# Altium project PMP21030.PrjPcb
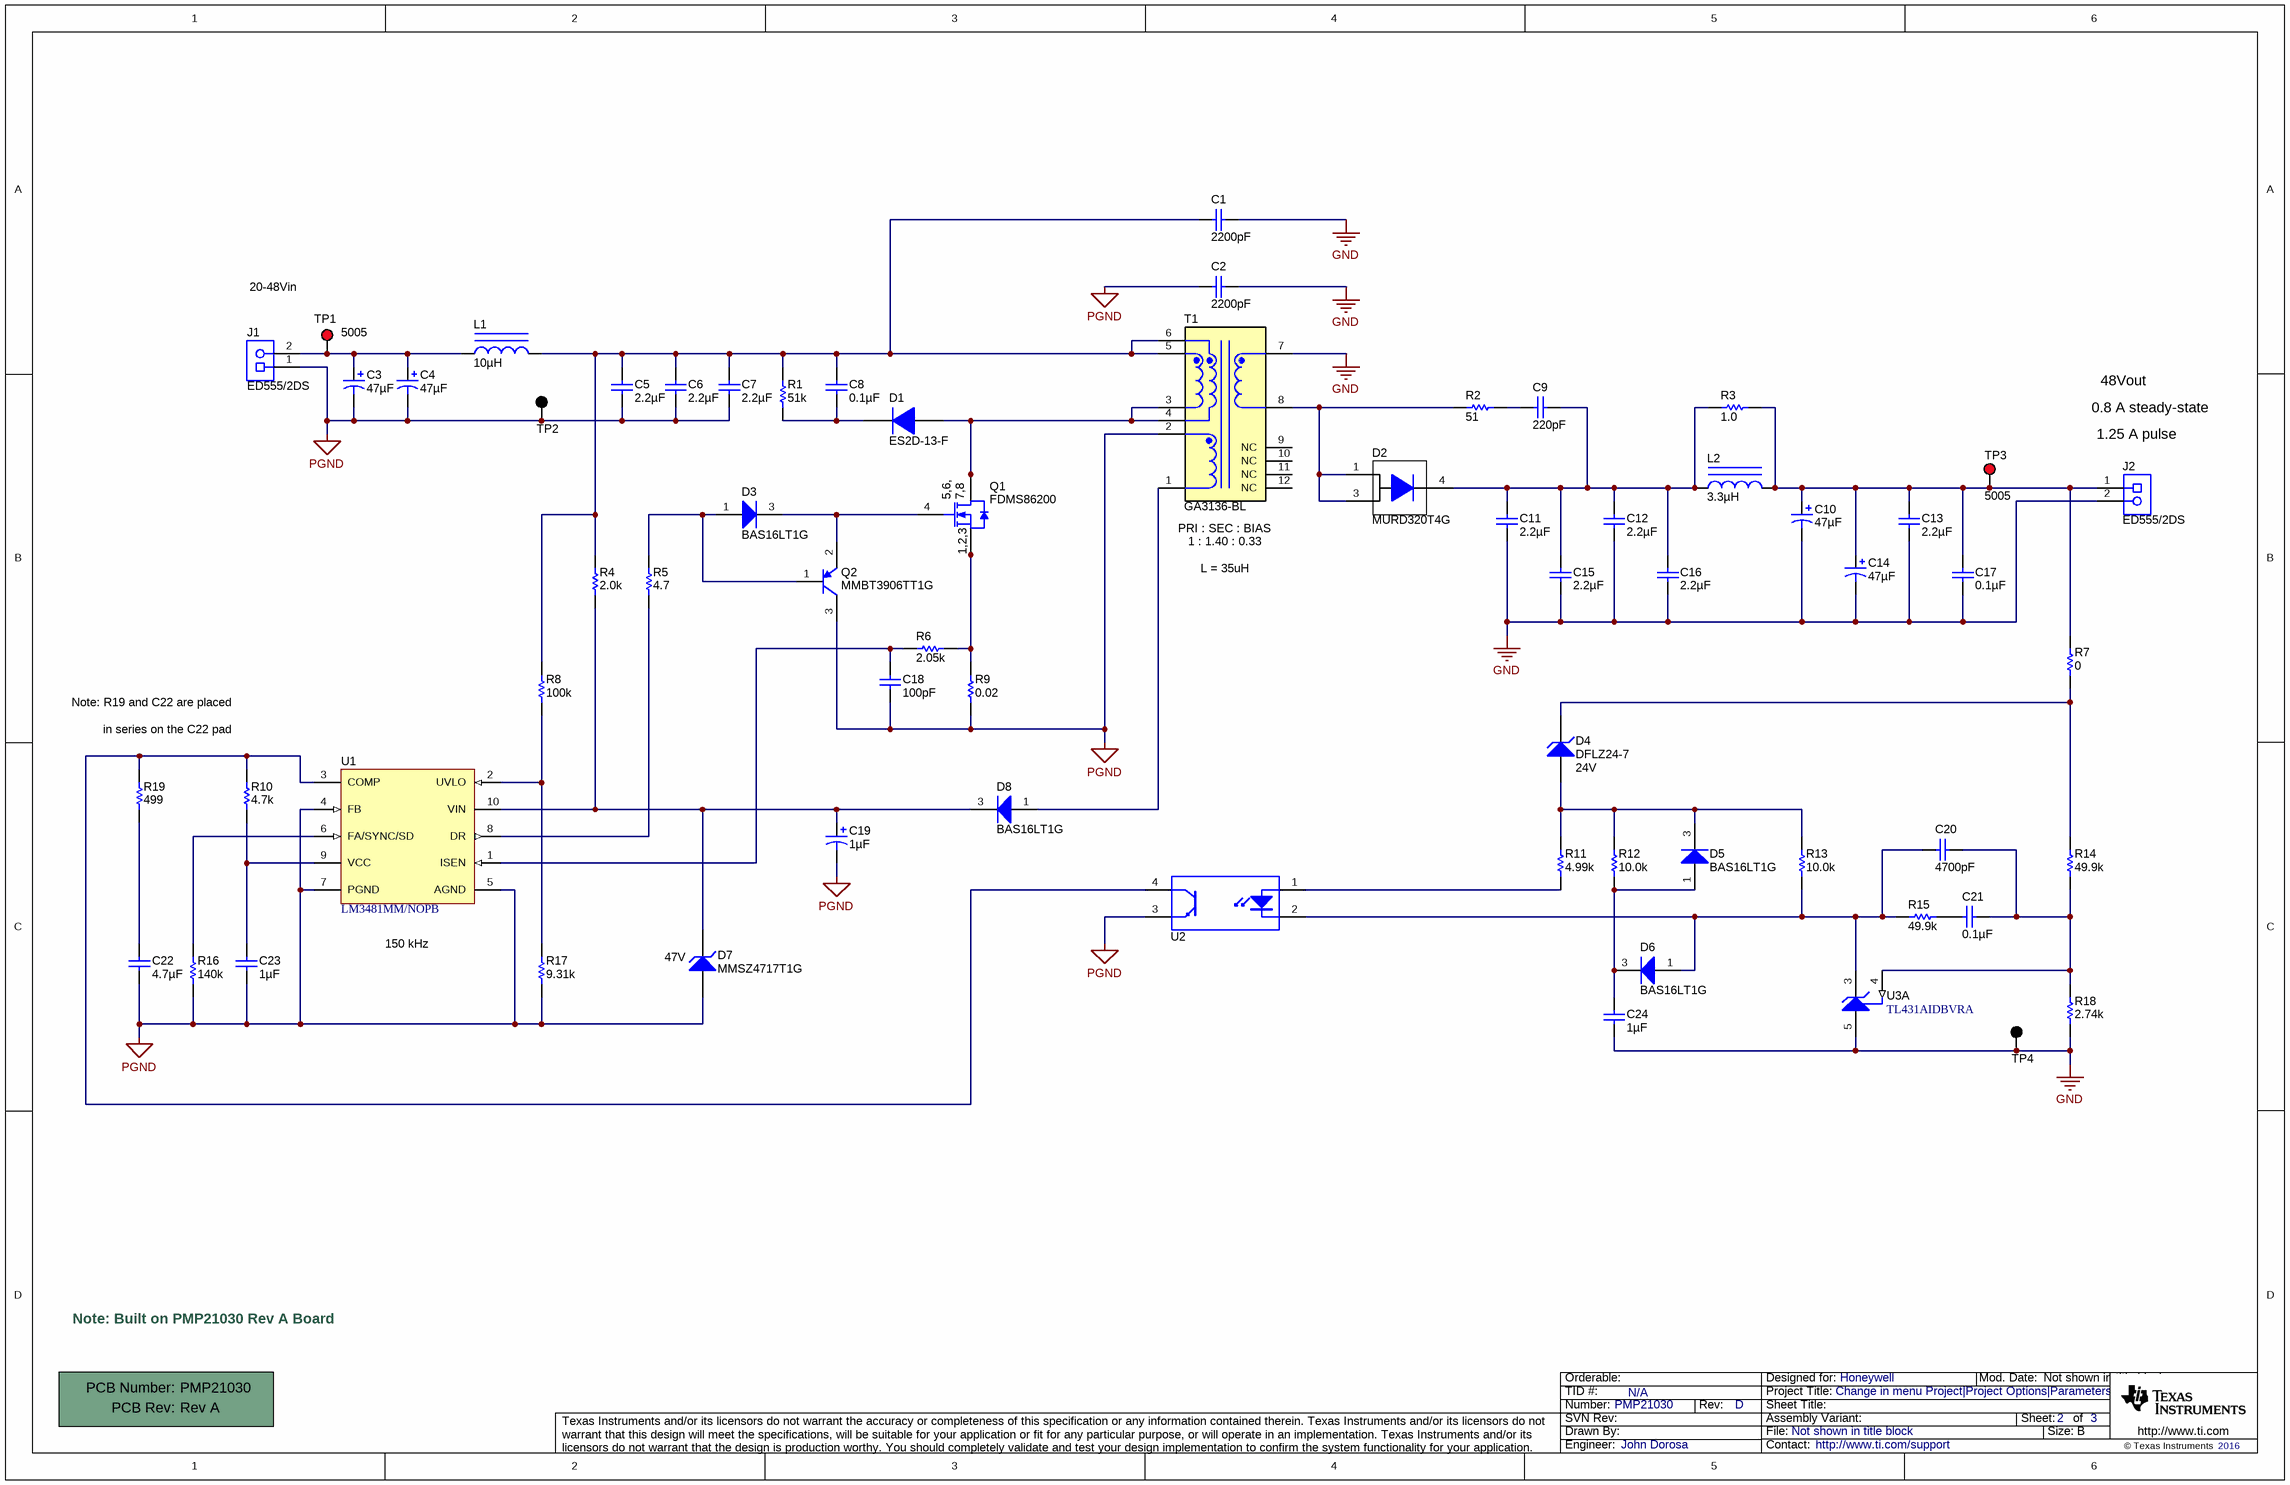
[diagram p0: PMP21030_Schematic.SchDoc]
TID: N/A; TechSupport: http://www.ti.com/support; SCH_Rev: D; PRJ_Title: Change in menu Project|Project Options|Parameters; PRJ_Number: PMP21030; PRJ_Engineer: John Dorosa; PRJ_Customer: Honeywell; PCB_Rev: Rev A; PCB_Layout: John Dorosa; CopyrightYear: 2016
1 sheet, 66 parts. Net scope: global (net labels, ports and power ports of the same name join across sheets).
Board file: PMP21030_PCB.PcbDoc

## Sheet PMP21030_Schematic.SchDoc
size 431 x 279 mm; Date: Not shown in title block; ApprovedBy: Not shown in title block; CheckedBy: Not shown in title block; Author: Not shown in title block; CompanyName: Not shown in title block; Engineer: Not shown in title block; Organization: Not shown in title block; Address1: Not shown in title block; Address2: Not shown in title block; Address3: Not shown in title block; Address4: Not shown in title block; DocumentNumber: 1; Revision: Use project parameter SCH_Rev; SheetNumber: 2; SheetTotal: 3; PageSetup: Record=PageOptions¦CenterHorizontal=True¦CenterVertical=True¦PrintScale=1.00¦XCorrection=1.00¦YCorrection=1.00¦PrintKind=0¦BorderSize=5000000¦LeftOffset=0¦BottomOffset=0¦Orientation=2¦PaperLength=1000¦PaperWidth=1000¦Scale=100¦PaperSource=15¦PrintQuality=600¦MediaType=1¦DitherType=10¦PaperKind=Letter¦PrintScaleMode=1

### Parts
!PCB  Printed Circuit Board  (value not drawn)  (mechanical)
C1  ValueDisplayed: 2200pF  [1812]  (hidden comment: C4532X7R3D222K130KA)
C2  ValueDisplayed: 2200pF  [1812]  (hidden comment: C4532X7R3D222K130KA)
C3  ValueDisplayed: 47µF  [SM_RADIAL_F]  (hidden comment: EEE-FK1J470P)
C4  ValueDisplayed: 47µF  [SM_RADIAL_F]  (hidden comment: EEE-FK1J470P)
C5  ValueDisplayed: 2.2µF  [1206l]  (hidden comment: C3216X7S2A225K160AB)
C6  ValueDisplayed: 2.2µF  [1206l]  (hidden comment: C3216X7S2A225K160AB)
C7  ValueDisplayed: 2.2µF  [1206l]  (hidden comment: C3216X7S2A225K160AB)
C8  ValueDisplayed: 0.1µF  [0603L]  (hidden comment: GCJ188R72A104KA01D)
C9  ValueDisplayed: 220pF  [1206L]  (hidden comment: GRM31A7U2J221JW31D)
C10  ValueDisplayed: 47µF  [SM_RADIAL_F]  (hidden comment: EEE-FK1J470P)
C11  ValueDisplayed: 2.2µF  [1206l]  (hidden comment: C3216X7S2A225K160AB)
C12  ValueDisplayed: 2.2µF  [1206l]  (hidden comment: C3216X7S2A225K160AB)
C13  ValueDisplayed: 2.2µF  [1206l]  (hidden comment: C3216X7S2A225K160AB)
C14  ValueDisplayed: 47µF  [SM_RADIAL_F]  (hidden comment: EEE-FK1J470P)
C15  ValueDisplayed: 2.2µF  [1206l]  (hidden comment: C3216X7S2A225K160AB)
C16  ValueDisplayed: 2.2µF  [1206l]  (hidden comment: C3216X7S2A225K160AB)
C17  ValueDisplayed: 0.1µF  [1206l]  (hidden comment: GRM31CR72D104KW03L)
C18  ValueDisplayed: 100pF  [0603L]  (hidden comment: GRM1885C2A101JA01D)
C19  ValueDisplayed: 1µF  [Chemi-Con_500x1100]  (hidden comment: EKMG101ELL1R0ME11D)
C20  ValueDisplayed: 4700pF  [0603L]  (hidden comment: GCM188R71H472KA37D)
C21  ValueDisplayed: 0.1µF  [0603L]  (hidden comment: C1608X7R1E104K080AA)
C22  ValueDisplayed: 4.7µF  [0402L]  (hidden comment: GRM155R61E475ME15)
C23  ValueDisplayed: 1µF  [0805L]  (hidden comment: GRM219R71E105KA88D)
C24  ValueDisplayed: 1µF  [0603L]  (hidden comment: GCM188R71E105KA64D)
D1  ES2D-13-F  [SMB]
D2  MURD320T4G  [DPAK]
D3  BAS16LT1G  [SOT-23]
D4  DFLZ24-7  value 24V  [PowerDI123]
D5  BAS16LT1G  [SOT-23]
D6  BAS16LT1G  [SOT-23]
D7  MMSZ4717T1G  [SOD-123]
D8  BAS16LT1G  [SOT-23]
J1  ED555/2DS  [TERM_BLK_ED555-2DS]
J2  ED555/2DS  [TERM_BLK_ED555-2DS]
L1  ValueDisplayed: 10µH  [MSS1048]  (hidden comment: MSS1048-103MLB)
L2  ValueDisplayed: 3.3µH  [LPS4018]  (hidden comment: LPS4018-332MLB)
Q1  FDMS86200  [TRANS_Fairchild_PQFN08A]
Q2  MMBT3906TT1G  [SOT-416]
R1  ValueDisplayed: 51k  [2010L]  (hidden comment: CRCW201051K0JNEF)
R2  ValueDisplayed: 51  [2512]  (hidden comment: CRCW251251R0JNEG)
R3  ValueDisplayed: 1.0  [1206]  (hidden comment: CRCW12061R00JNEA)
R4  ValueDisplayed: 2.0k  [0805L]  (hidden comment: CRCW08052K00JNEA)
R5  ValueDisplayed: 4.7  [0603L]  (hidden comment: CRCW06034R70JNEA)
R6  ValueDisplayed: 2.05k  [0603L]  (hidden comment: CRCW06032K05FKEA)
R7  ValueDisplayed: 0  [0603L]  (hidden comment: CRCW06030000Z0EA)
R8  ValueDisplayed: 100k  [0603L]  (hidden comment: CRCW0603100KFKEA)
R9  ValueDisplayed: 0.02  [1206L]  (hidden comment: WSLP1206R0200FEA)
R10  ValueDisplayed: 4.7k  [0805L]  (hidden comment: CRCW08054K70JNEA)
R11  ValueDisplayed: 4.99k  [0603L]  (hidden comment: CRCW06034K99FKEA)
R12  ValueDisplayed: 10.0k  [0603L]  (hidden comment: CRCW060310K0FKEA)
R13  ValueDisplayed: 10.0k  [0603L]  (hidden comment: CRCW060310K0FKEA)
R14  ValueDisplayed: 49.9k  [0603L]  (hidden comment: CRCW060349K9FKEA)
R15  ValueDisplayed: 49.9k  [0603L]  (hidden comment: CRCW060349K9FKEA)
R16  ValueDisplayed: 140k  [0603L]  (hidden comment: CRCW0603140KFKEA)
R17  ValueDisplayed: 9.31k  [0603L]  (hidden comment: CRCW06039K31FKEA)
R18  ValueDisplayed: 2.74k  [0603L]  (hidden comment: CRCW06032K74FKEA)
R19  ValueDisplayed: 499  [0402L]  (hidden comment: CRCW0402499RFKED)
T1  GA3136-BL  [Coilcraft_GA3136-BL]
TP1  5005  [Keystone5005]
TP2  5006  [Keystone5006]  (value not drawn)
TP3  5005  [Keystone5005]
TP4  5006  [Keystone5006]  (value not drawn)
U1  LM3481MM/NOPB  [MUB10A_N]
U2  TCMT1107  [SOP-4]  (value not drawn)
U3  TL431AIDBVRA  [DBV0005A_N]  (part A of 2)

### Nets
GND: C1.1 C2.1 C10.2(-) C11.2 C12.2 C13.2 C14.2(-) C15.2 C16.2 C17.2 C24.2 J2.2 R18.1 T1.7 TP4.1 U3.5(ANODE)
PGND: C2.2 C3.2(-) C4.2(-) C5.2 C6.2 C7.2 C18.2 C19.2(-) C22.2 C23.2 D7.2(A) J1.1 Q2.3(C) R9.1 R16.2 R17.1 T1.2 TP2.1 U1.4(FB) U1.5(AGND) U1.7(PGND) U2.3(E)
NetC1_2: C1.2 C5.1 C6.1 C7.1 C8.1 L1.2 R1.2 R4.2 R8.2 T1.5 T1.6
NetC3_1: C3.1(+) C4.1(+) J1.2 L1.1 TP1.1
NetC8_2: C8.2 D1.1(K) R1.1
NetC9_1: C9.1 C11.1 C12.1 C15.1 C16.1 D2.4(K) L2.1 R3.1
NetC9_2: C9.2 R2.2
NetC10_1: C10.1(+) C13.1 C14.1(+) C17.1 J2.1 L2.2 R3.2 R7.2 TP3.1
NetC18_1: C18.1 R6.1 U1.1(ISEN)
NetC19_1: C19.1(+) D7.1(K) D8.3(K) R4.1 U1.10(VIN)
NetC20_1: C20.1 C21.1 R14.1 R18.2 U3.4(REF)
NetC20_2: C20.2 D6.1(A) R13.1 R15.2 U2.2(K) U3.3(CATHODE)
NetC21_2: C21.2 R15.1
NetC22_1: C22.1 R19.1
NetC23_1: C23.1 R10.1 U1.9(VCC)
NetC24_1: C24.1 D5.1(A) D6.3(K) R12.1
NetD1_2: D1.2(A) Q1.5(D) Q1.6(D) Q1.7(D) Q1.8(D) T1.3 T1.4
NetD2_1: D2.1(A) D2.3(A) R2.1 T1.8
NetD3_1: D3.1(A) Q2.1(B) R5.2
NetD3_3: D3.3(K) Q1.4(G) Q2.2(E)
NetD4_1: D4.1(K) R7.1 R14.2
NetD4_2: D4.2(A) D5.3(K) R11.2 R12.2 R13.2
NetD8_1: D8.1(A) T1.1
NetQ1_1: Q1.1(S) Q1.2(S) Q1.3(S) R6.2 R9.2
NetR5_1: R5.1 U1.8(DR)
NetR8_1: R8.1 R17.2 U1.2(UVLO)
NetR10_2: R10.2 R19.2 U1.3(COMP) U2.4(C)
NetR11_1: R11.1 U2.1(A)
NetR16_1: R16.1 U1.6(FA/SYNC/SD)

Not connected (* = marked no-connect by the designer): T1 9(NC) 10(NC) 11(NC) 12(NC)

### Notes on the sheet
- 20-48Vin
- 48Vout
- (near J2) 1.25 A pulse
- 0.8 A steady-state
- (near T1) PRI : SEC : BIAS
- (near T1) 1 : 1.40 : 0.33
- L = 35uH
- Note: R19 and C22 are placed
- in series on the C22 pad
- (near U1) 150 kHz
- (near D7) 47V
- Note: Built on PMP21030 Rev A Board

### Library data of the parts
!PCB = PCB: Manufacturer: Any; PartNumber: PMP21030; SymbolCreator: a0412235
C1 C2 = C4532X7R3D222K130KA: CAP, CERM, 2200 pF, 2000 V,+/- 10%, X7R, 1812; Manufacturer: TDK; Polarized: N; CompType: Capacitor; Value: 2200pF; U/M: EA; Cap_F: 0.0000000022; Tolerance_%: 10; VDC_V: 2000; Value2: 2000V; TaMin_C: -55; TaMax_C: 125; SizeArea_mm2: 14.4; SizeAreaWB_mm2: 23.1; SizeX_mm: 4.5; SizeY_mm: 3.2; SizeZ_mm: 1.35; AEC Category: Q200; Green_Lifecycle: Active; Green_REACh: Passed
C3 C4 C10 C14 = EEE-FK1J470P: CAP, AL, 47 µF, 63 V, +/- 20%, 0.65 ohm, AEC-Q200 Grade 2, SMD; Manufacturer: Panasonic; Polarized: Y; CompType: Capacitor; Value: 47uF; U/M: EA; Cap_F: 0.000047; Tolerance_%: 20; VDC_V: 63; Value2: 63V; ESR_ohm: 0.65; IRMS_A: 0.25; TaMin_C: -55; TaMax_C: 105; Cap_Case: F; SizeAreaWB_mm2: 123.6; SizeArea_mm2: 83; SizeX_mm: 10; SizeY_mm: 8.3; SizeZ_mm: 10.2; AEC Category: Q200; AEC Grade: 2; Green_Lifecycle: Active; Green_REACh: Passed
C5-C7 C11-C13 C15 C16 = C3216X7S2A225K160AB: CAP, CERM, 2.2 µF, 100 V,+/- 10%, X7S, 1206; Manufacturer: TDK; Polarized: N; CompType: Capacitor; Value: 2.2uF; U/M: EA; Cap_F: 0.0000022; Tolerance_%: 10; ESR_ohm: 0.005718; Value1: 0.005718 ohm; VDC_V: 100; Value2: 100V; IRMS_A: 3.03632; TaMin_C: -55; TaMax_C: 125; Cap_Case: 1206; SizeArea_mm2: 5.12; SizeAreaWB_mm2: 10.92; SizeX_mm: 3.2; SizeY_mm: 1.6; SizeZ_mm: 1.8; AEC Category: Q200
C8 = GCJ188R72A104KA01D: CAP, CERM, 0.1 µF, 100 V,+/- 10%, X7R, AEC-Q200 Grade 1, 0603; Manufacturer: MuRata; Polarized: N; CompType: Capacitor; Value: 0.1uF; U/M: EA; Cap_F: 0.0000001; Tolerance_%: 10; VDC_V: 100; Value2: 100V; TaMin_C: -55; TaMax_C: 125; Cap_Case: 0603; SizeArea_mm2: 1.28; SizeAreaWB_mm2: 4.68; SizeX_mm: 1.6; SizeY_mm: 0.8; SizeZ_mm: 1; AEC Category: Q200; AEC Qualified: Y
C9 = GRM31A7U2J221JW31D: CAP, CERM, 220 pF, 630 V,+/- 5%, U2J, 1206; Manufacturer: MuRata; Polarized: N; CompType: Capacitor; Value: 220pF; U/M: EA; Cap_F: 0.00000000022; Tolerance_%: 5; VDC_V: 630; Value2: 630V; TaMin_C: -55; TaMax_C: 125; Cap_Case: 1206; SizeArea_mm2: 5.12; SizeAreaWB_mm2: 10.92; SizeX_mm: 3.2; SizeY_mm: 1.6; SizeZ_mm: 1.35; AEC Category: Q200
C17 = GRM31CR72D104KW03L: CAP, CERM, 0.1 µF, 200 V,+/- 10%, X7R, 1206; Manufacturer: MuRata; Polarized: N; CompType: Capacitor; Value: 0.1uF; U/M: EA; Cap_F: 0.0000001; Tolerance_%: 10; VDC_V: 200; Value2: 200V; TaMin_C: -55; TaMax_C: 125; Cap_Case: 1206; SizeArea_mm2: 5.12; SizeAreaWB_mm2: 10.92; SizeX_mm: 3.2; SizeY_mm: 1.6; SizeZ_mm: 1.8; AEC Category: Q200
C18 = GRM1885C2A101JA01D: CAP, CERM, 100 pF, 100 V,+/- 5%, C0G/NP0, 0603; Manufacturer: MuRata; Polarized: N; CompType: Capacitor; Value: 100pF; U/M: EA; Cap_F: 0.0000000001; Tolerance_%: 5; VDC_V: 100; Value2: 100V; TaMin_C: -55; TaMax_C: 125; Cap_Case: 0603; SizeArea_mm2: 1.28; SizeAreaWB_mm2: 4.68; SizeX_mm: 1.6; SizeY_mm: 0.8; SizeZ_mm: 1; AEC Category: Q200; Green_Lifecycle: Active; Green_REACh: Passed
C19 = EKMG101ELL1R0ME11D: CAP, AL, 1 µF, 100 V, +/- 20%, TH; Manufacturer: Chemi-Con; Polarized: Y; CompType: Capacitor; Value: 1uF; U/M: EA; Cap_F: 0.000001; Tolerance_%: 20; VDC_V: 100; Value2: 100V; IRMS_A: 0.015; TaMin_C: -55; TaMax_C: 105; Cap_Case: 5x11mm; SizeAreaWB_mm2: 49; SizeArea_mm2: 25; SizeX_mm: 5; SizeZ_mm: 12.5; AEC Category: Q200; AEC Qualified: N
C20 = GCM188R71H472KA37D: CAP, CERM, 4700 pF, 50 V,+/- 10%, X7R, AEC-Q200 Grade 1, 0603; Manufacturer: MuRata; Polarized: N; CompType: Capacitor; Value: 4700pF; U/M: EA; Cap_F: 0.0000000047; Tolerance_%: 10; VDC_V: 50; Value2: 50V; TaMin_C: -55; TaMax_C: 125; Cap_Case: 0603; SizeArea_mm2: 1.28; SizeAreaWB_mm2: 4.68; SizeX_mm: 1.6; SizeY_mm: 0.8; SizeZ_mm: 1; AEC Category: Q200; AEC Qualified: Y
C21 = C1608X7R1E104K080AA: CAP, CERM, 0.1 µF, 25 V,+/- 10%, X7R, 0603; Manufacturer: TDK; Polarized: N; CompType: Capacitor; Value: 0.1uF; U/M: EA; Cap_F: 0.0000001; Tolerance_%: 10; VDC_V: 25; Value2: 25V; TaMin_C: -55; TaMax_C: 125; Cap_Case: 0603; SizeArea_mm2: 1.28; SizeAreaWB_mm2: 4.68; SizeX_mm: 1.6; SizeY_mm: 0.8; SizeZ_mm: 1; AEC Category: Q200; Green_Lifecycle: NRND; Green_REACh: Passed
C22 = GRM155R61E475ME15: CAP, CERM, 4.7 µF, 25 V,+/- 20%, X5R, 0402; Manufacturer: MuRata; Polarized: N; CompType: Capacitor; Value: 4.7uF; U/M: EA; Cap_F: 0.0000047; Tolerance_%: 20; VDC_V: 25; Value2: 25V; TaMin_C: -55; TaMax_C: 85; Cap_Case: 0402; SizeArea_mm2: 0.5; SizeAreaWB_mm2: 3; SizeX_mm: 1; SizeZ_mm: 0.6; AEC Category: Q200
C23 = GRM219R71E105KA88D: CAP, CERM, 1 µF, 25 V,+/- 10%, X7R, 0805; Manufacturer: MuRata; Polarized: N; CompType: Capacitor; Value: 1uF; U/M: EA; Cap_F: 0.000001; Tolerance_%: 10; VDC_V: 25; Value2: 25V; TaMin_C: -55; TaMax_C: 125; Cap_Case: 0805; SizeArea_mm2: 2.5; SizeAreaWB_mm2: 6.75; SizeX_mm: 2; SizeY_mm: 1.25; SizeZ_mm: 1.45; AEC Category: Q200; Green_Lifecycle: Active; Green_REACh: Passed
C24 = GCM188R71E105KA64D: CAP, CERM, 1 µF, 25 V,+/- 10%, X7R, AEC-Q200 Grade 1, 0603; Manufacturer: MuRata; Polarized: N; CompType: Capacitor; Value: 1uF; U/M: EA; Cap_F: 0.000001; Tolerance_%: 10; VDC_V: 25; Value2: 25V; TaMin_C: -55; TaMax_C: 125; Cap_Case: 0603; SizeArea_mm2: 1.28; SizeAreaWB_mm2: 4.68; SizeX_mm: 1.6; SizeY_mm: 0.8; SizeZ_mm: 1; AEC Category: Q200; AEC Qualified: Y
D1 = ES2D-13-F: Diode, Ultrafast, 200 V, 2 A, SMB; Manufacturer: Diodes Inc.; U/M: EA; Vf_V: 0.92; Value: 200V; Value1: 2A; Value2: 0.92V; Io_A: 2; Vr_V: 200; TJmax_C: 150; RJC_CperW: 20; SizeAreaWB_mm2: 44.156; SizeArea_mm2: 21.336; SizeX_mm: 5.6; SizeY_mm: 3.81; SizeZ_mm: 2.6; AEC Category: Q101; Green_Lifecycle: Active; Green_REACh: Passed
D2 = CMP-0074782-1: Diode, Ultrafast, 200 V, 3 A, AEC-Q101, DPAK; Manufacturer: ON Semiconductor; Io_A: 3A; SizeAreaWB_mm2: 101.7114; Vr_V: 200V; TJmax_C: 175°C; U/M: EA; Value: 200V; SizeZ_mm: 2.29; SizeX_mm: 9.91; SizeY_mm: 6.54; Vf_V: 9.5dV; Value2: 0.95V; SizeArea_mm2: 64.8114; AEC Qualified: Y; AEC Category: Q101; RJC_CperW: 6.0
D3 D5 D6 D8 = BAS16LT1G: Diode, Switching, 100 V, 0.2 A, SOT-23; Manufacturer: ON Semiconductor; U/M: EA; Vf_V: 1.25; Value: 100V; Value1: 0.2A; Value2: 1.25V; Io_A: 0.2; Vr_V: 100; TJmax_C: 150; SizeAreaWB_mm2: 14; SizeArea_mm2: 7.5; SizeX_mm: 2.5; SizeY_mm: 3; SizeZ_mm: 1.1; AEC Category: Q101; AEC Qualified: N; Green_Lifecycle: Active; Green_REACh: Passed
D4 = DFLZ24-7: Diode, Zener, 24 V, 1 W, PowerDI123; Manufacturer: Diodes Inc.; SymbolCreator: a0412235; U/M: EA; Power_W: 1; Vz_V: 24; Value1: 1W; RJA_CperW: 110; SizeAreaWB_mm2: 13.066; SizeArea_mm2: 6.586; SizeX_mm: 3.7; SizeY_mm: 1.78; SizeZ_mm: 0.98; AEC Category: Q101
D7 = CMP-0005748-2: Diode, Zener, 43 V, 500 mW, SOD-123; Manufacturer: ON Semiconductor; Power_W: 500mW; SizeAreaWB_mm2: 13.095; Vz_V: 43V; Value1: 0.5W; RJA_CperW: 340; U/M: EA; Value: 43V; SizeZ_mm: 1.35; SizeX_mm: 3.85; SizeY_mm: 1.7; SizeArea_mm2: 6.545; AEC Category: Q101
J1 J2 = ED555/2DS: Terminal Block, 3.5mm Pitch, 2x1, TH; Manufacturer: On-Shore Technology; SymbolCreator: a0412235; Pitch_mm: 3.5; Gender: Female; Shrouded: N; Row_Count: 1; ContactFinish: Brass; Current_A: 6; Voltage_V: 150; Cert_CULUS: Y; Green_Lifecycle: Active; Green_REACh: Passed
L1 = MSS1048-103MLB: Inductor, Shielded Drum Core, Ferrite, 10 µH, 4.32 A, 0.03 ohm, SMD; Manufacturer: Coilcraft; Value: 10uH; Ind_H: 10.0E-6; Imax_A: 4.32; Irms: 4.79A @ 40C rise; Isat: 4.32A @ 30% inductance drop; DCR_ohm: 0.03; Value2: 4.32A; SizeAreaWB_mm2: 146.4; SizeArea_mm2: 102; SizeX_mm: 10.2; SizeY_mm: 10; SizeZ_mm: 4.8; AEC Category: Q200; Green_Lifecycle: Not Set; Green_REACh: Incomplete
L2 = LPS4018-332MLB: Inductor, Shielded Drum Core, Ferrite, 3.3 µH, 1.9 A, 0.08 ohm, SMD; Manufacturer: Coilcraft; Value: 3.3uH; Ind_H: 3.3E-6; Imax_A: 1.9; Irms: 1.9A @ 40C rise; Isat: 2A @ 30% inductance drop; DCR_ohm: 0.08; Value2: 1.9A; SizeAreaWB_mm2: 24.01; SizeArea_mm2: 15.21; SizeX_mm: 3.9; SizeZ_mm: 1.7; AEC Category: Q200; Green_Lifecycle: Not Set; Green_REACh: Incomplete
Q1 = FDMS86200: MOSFET, N-CH, 150 V, 35 A, PQFN08A; Manufacturer: Fairchild Semiconductor; Alternate Manufacturer: None; U/M: EA; ChType: N; Value: 150V; VdsMax_V: 150; Value1: ? ohm; Value2: 33 nC; QgTyp_nC: 33; Vgs_V: 20; IdsMax_A: 35; SizeAreaWB_mm2: 56; SizeArea_mm2: 30; SizeX_mm: 5; SizeY_mm: 6; SizeZ_mm: 1.1; AEC Category: Q101; Green_Lifecycle: Active; Green_REACh: Passed
Q2 = MMBT3906TT1G, ON Semiconductor: Transistor, PNP, 40 V, 0.2 A, SOT-416; CompType: BJT; PNP: 1; NPN: 0; Vceo_V: 40; Vcesat1_V: 0.25; Value: 40 V; IcRated_A: 0.2; Value1: 0.2 A; HfeMax: 300; TaMin_C: -55; TaMax_C: 150; SizeAreaWB_mm2: 6.76; SizeArea_mm2: 2.56; SizeX_mm: 1.6; SizeZ_mm: 0.95; U/M: EA; AEC Category: Q101; AEC Qualified: N
R1 = CRCW201051K0JNEF: RES, 51 k, 5%, 0.75 W, AEC-Q200 Grade 0, 2010; Manufacturer: Vishay-Dale; CompType: Resistor; Value: 51k; Res_ohm: 51000; Value_Code: 51k0; Tolerance_%: 5; Power_W: 0.75; Value2: 0.75W; VDC_V: 400; TempCo: 200 ppm/C; SizeArea_mm2: 12.5; SizeY_mm: 2.5; SizeZ_mm: 1.66; EIA_Code: E24; U/M: EA; AEC Category: Q200; AEC Qualified: Y; AEC Grade: 0
R2 = CRCW251251R0JNEG: RES, 51, 5%, 1 W, AEC-Q200 Grade 0, 2512; Manufacturer: Vishay-Dale; CompType: Resistor; Value: 51; Value_Code: 51R0; Tolerance_%: 5; Power_W: 1; Value2: 1W; VDC_V: 500; TempCo: 200 ppm/C; SizeArea_mm2: 20.16; SizeX_mm: 6.3; SizeY_mm: 3.2; SizeZ_mm: 0.71; EIA_Code: E24; U/M: EA; AEC Category: Q200; AEC Qualified: Y; AEC Grade: 0
R3 = CRCW12061R00JNEA: RES, 1.0, 5%, 0.25 W, 1206; Manufacturer: Vishay-Dale; CompType: Resistor; Value: 1.0; Res_ohm: 1; Value_Code: 1R00; Tolerance_%: 5; Power_W: 0.25; Value2: 0.25W; VDC_V: 200; TempCo: 200 ppm/C; SizeArea_mm2: 5.12; SizeX_mm: 3.2; SizeY_mm: 1.6; SizeZ_mm: 1.35; EIA_Code: E24; U/M: EA; AEC Category: Q200; Green_Lifecycle: Active; Green_REACh: Passed
R4 = CRCW08052K00JNEA: RES, 2.0 k, 5%, 0.125 W, 0805; Manufacturer: Vishay-Dale; CompType: Resistor; Value: 2.0k; Res_ohm: 2000; Value_Code: 2k00; Tolerance_%: 5; Power_W: 0.125; Value2: 0.125W; VDC_V: 150; TempCo: 200 ppm/C; SizeArea_mm2: 2.5; SizeX_mm: 2; SizeY_mm: 1.25; SizeZ_mm: 1.45; EIA_Code: E24; U/M: EA; AEC Category: Q200; Green_Lifecycle: Active; Green_REACh: Passed
R5 = CRCW06034R70JNEA: RES, 4.7, 5%, 0.1 W, 0603; Manufacturer: Vishay-Dale; CompType: Resistor; Value: 4.7; Value_Code: 4R70; Tolerance_%: 5; Power_W: 0.1; Value2: 0.1W; VDC_V: 75; TempCo: 200 ppm/C; SizeArea_mm2: 1.28; SizeX_mm: 1.6; SizeY_mm: 0.8; SizeZ_mm: 1; EIA_Code: E24; U/M: EA; AEC Category: Q200; Green_Lifecycle: Active; Green_REACh: Passed
R6 = CRCW06032K05FKEA: RES, 2.05 k, 1%, 0.1 W, 0603; Manufacturer: Vishay-Dale; CompType: Resistor; Value: 2.05k; Res_ohm: 2050; Value_Code: 2k05; Tolerance_%: 1; Power_W: 0.1; Value2: 0.1W; VDC_V: 75; TempCo: 100 ppm/C; SizeArea_mm2: 1.28; SizeX_mm: 1.6; SizeY_mm: 0.8; EIA_Code: E96; U/M: EA; AEC Category: Q200; Green_Lifecycle: Active; Green_REACh: Passed
R7 = CRCW06030000Z0EA: RES, 0, 5%, 0.1 W, 0603; Manufacturer: Vishay-Dale; CompType: Resistor; Value: 0; Value_Code: 0000; Tolerance_%: 5; Power_W: 0.1; Value2: 0.1W; VDC_V: 75; TempCo: 200 ppm/C; SizeArea_mm2: 1.28; SizeX_mm: 1.6; SizeY_mm: 0.8; SizeZ_mm: 1; EIA_Code: E24; U/M: EA; AEC Category: Q200; Green_Lifecycle: Active; Green_REACh: Passed
R8 = CRCW0603100KFKEA: RES, 100 k, 1%, 0.1 W, 0603; Manufacturer: Vishay-Dale; CompType: Resistor; Value: 100k; Res_ohm: 100000; Tolerance_%: 1; Power_W: 0.1; Value2: 0.1W; VDC_V: 75; TempCo: 100 ppm/C; SizeArea_mm2: 1.28; SizeX_mm: 1.6; SizeY_mm: 0.8; EIA_Code: E96; U/M: EA; AEC Category: Q200; Green_Lifecycle: Active; Green_REACh: Passed
R9 = WSLP1206R0200FEA: RES, 0.02, 1%, 1 W, 1206; Manufacturer: Vishay-Dale; CompType: Resistor; Value: 0.02; Value_Code: R020; Tolerance_%: 1; Value2: 1W; TempCo: 75 ppm/C; SizeArea_mm2: 5.12; SizeX_mm: 3.2; SizeY_mm: 1.6; SizeZ_mm: 1.35; EIA_Code: E96; U/M: EA; AEC Category: Q200
R10 = CRCW08054K70JNEA: RES, 4.7 k, 5%, 0.125 W, 0805; Manufacturer: Vishay-Dale; CompType: Resistor; Value: 4.7k; Res_ohm: 4700; Value_Code: 4k70; Tolerance_%: 5; Power_W: 0.125; Value2: 0.125W; VDC_V: 150; TempCo: 200 ppm/C; SizeArea_mm2: 2.5; SizeX_mm: 2; SizeY_mm: 1.25; SizeZ_mm: 1.45; EIA_Code: E24; U/M: EA; AEC Category: Q200; Green_Lifecycle: Active; Green_REACh: Passed
R11 = CRCW06034K99FKEA: RES, 4.99 k, 1%, 0.1 W, 0603; Manufacturer: Vishay-Dale; CompType: Resistor; Value: 4.99k; Res_ohm: 4990; Value_Code: 4k99; Tolerance_%: 1; Power_W: 0.1; Value2: 0.1W; VDC_V: 75; TempCo: 100 ppm/C; SizeArea_mm2: 1.28; SizeX_mm: 1.6; SizeY_mm: 0.8; EIA_Code: E96; U/M: EA; AEC Category: Q200; Green_Lifecycle: Active; Green_REACh: Passed
R12 R13 = CRCW060310K0FKEA: RES, 10.0 k, 1%, 0.1 W, 0603; Manufacturer: Vishay-Dale; CompType: Resistor; Value: 10.0k; Res_ohm: 10000; Value_Code: 10k0; Tolerance_%: 1; Power_W: 0.1; Value2: 0.1W; VDC_V: 75; TempCo: 100 ppm/C; SizeArea_mm2: 1.28; SizeX_mm: 1.6; SizeY_mm: 0.8; EIA_Code: E96; U/M: EA; AEC Category: Q200; Green_Lifecycle: Active; Green_REACh: Passed
R14 R15 = CRCW060349K9FKEA: RES, 49.9 k, 1%, 0.1 W, 0603; Manufacturer: Vishay-Dale; CompType: Resistor; Value: 49.9k; Res_ohm: 49900; Value_Code: 49k9; Tolerance_%: 1; Power_W: 0.1; Value2: 0.1W; VDC_V: 75; TempCo: 100 ppm/C; SizeArea_mm2: 1.28; SizeX_mm: 1.6; SizeY_mm: 0.8; EIA_Code: E96; U/M: EA; AEC Category: Q200; Green_Lifecycle: Active; Green_REACh: Passed
R16 = CRCW0603140KFKEA: RES, 140 k, 1%, 0.1 W, 0603; Manufacturer: Vishay-Dale; CompType: Resistor; Value: 140k; Res_ohm: 140000; Tolerance_%: 1; Power_W: 0.1; Value2: 0.1W; VDC_V: 75; TempCo: 100 ppm/C; SizeArea_mm2: 1.28; SizeX_mm: 1.6; SizeY_mm: 0.8; EIA_Code: E96; U/M: EA; AEC Category: Q200; Green_Lifecycle: Active; Green_REACh: Passed
R17 = CRCW06039K31FKEA: RES, 9.31 k, 1%, 0.1 W, 0603; Manufacturer: Vishay-Dale; CompType: Resistor; Value: 9.31k; Res_ohm: 9310; Value_Code: 9k31; Tolerance_%: 1; Power_W: 0.1; Value2: 0.1W; VDC_V: 75; TempCo: 100 ppm/C; SizeArea_mm2: 1.28; SizeX_mm: 1.6; SizeY_mm: 0.8; EIA_Code: E96; U/M: EA; AEC Category: Q200; Green_Lifecycle: Active; Green_REACh: Passed
R18 = CRCW06032K74FKEA: RES, 2.74 k, 1%, 0.1 W, 0603; Manufacturer: Vishay-Dale; CompType: Resistor; Value: 2.74k; Res_ohm: 2740; Value_Code: 2k74; Tolerance_%: 1; Power_W: 0.1; Value2: 0.1W; VDC_V: 75; TempCo: 100 ppm/C; SizeArea_mm2: 1.28; SizeX_mm: 1.6; SizeY_mm: 0.8; EIA_Code: E96; U/M: EA; AEC Category: Q200; Green_Lifecycle: Active; Green_REACh: Passed
R19 = CRCW0402499RFKED: RES, 499, 1%, 0.063 W, 0402; Manufacturer: Vishay-Dale; CompType: Resistor; Value: 499; Value_Code: 499R; Tolerance_%: 1; Power_W: 0.063; Value2: 0.063W; VDC_V: 50; TempCo: 100 ppm/C; SizeArea_mm2: 0.5; SizeZ_mm: 0.6; EIA_Code: E96; U/M: EA; AEC Category: Q200; Green_Lifecycle: Active; Green_REACh: Passed
T1 = CMP-0074777-1: Transformer, Flyback, 35 uH, SMD; Manufacturer: Coilcraft; LeakageInd_H: 230nH; SizeAreaWB_mm2: 996.1875; DCR_ohm: 0.029; Value: 35uH; Lp: 35.0; SizeZ_mm: 14.0; SizeX_mm: 32.65; SizeY_mm: 26.75; Ns1toNp: 1.4; SizeArea_mm2: 873.3875; Ind_H: 35µH; AEC Qualified: N; Rsec1_ohm: 0.074; AEC Category: Q200
TP1 TP3 = CMP-0055142-1: Test Point, Compact, Red, TH; Manufacturer: Keystone; CNHeader: FALSE; Green_Lifecycle: Active; Green_REACh: Passed; ContactFinish: Silver; CT: TRUE
TP2 TP4 = 5006: Test Point, Compact, Black, TH; Manufacturer: Keystone; CompType: Test Point Loop; ContactFinish: Silver; Green_Lifecycle: Active; Green_REACh: Passed
U1 = LM3481MM/NOPB: High Efficiency Low-Side N-Channel Controller for Switching Regulators, 10-pin MSOP, Pb-Free; Manufacturer: Texas Instruments; PackageTopMarking: ZXTT*SJPB; PowerWise: N; CompType: MiscPower
U2 = TCMT1107: Optocoupler, 3.75 kV, 80-160% CTR, SMT; Manufacturer: Vishay-Semiconductor; CTR (Min): 80%; CTR (Max): 160%; Voltage_Isolation_Vrms: 3750V; SizeAreaWB_mm2: 43.65; SizeArea_mm2: 19.95; SizeX_mm: 7; SizeY_mm: 2.85; SizeZ_mm: 2.3
U3 = TL431AIDBVR: Adjustable Precision Shunt Regulator, 34 ppm / degC, 100 mA, -40 to 85 degC, 5-pin SOT-23 (DBV), Green (RoHS & no Sb/Br); Manufacturer: Texas Instruments; Alternate PartNumber: Equivalent; Initial Accuracy @ 25/deg C(%): 1; Iout/Iz(Max)(mA): 100; Min Iz for Regulation(uA): 600; Rating: Catalog; SubFamily: Shunt Voltage Reference; Temp Coeff(Max)(ppm/ degree C): 92; Temp Coeff(Typ)(ppm/ degree C): 34; VO Adj(Max)(V): 36; VO Adj(Min)(V): 2.495

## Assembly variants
001: not fitted FID1 FID2 FID3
